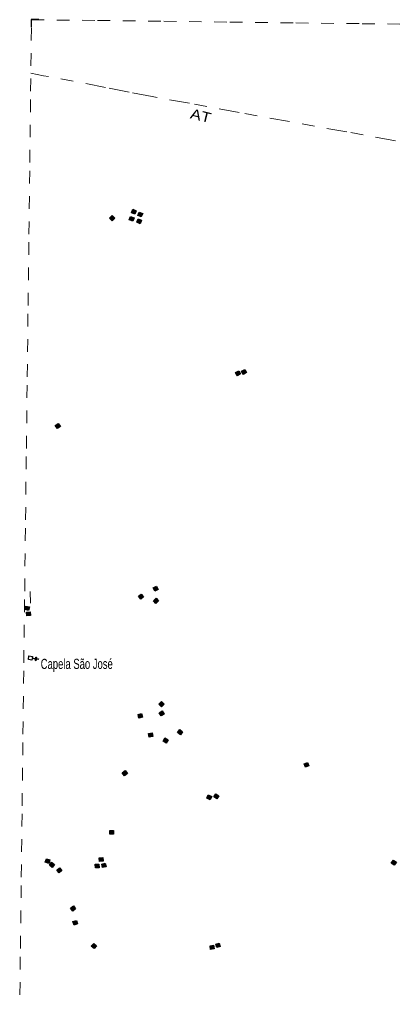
# Model space of a CAD drawing. Extents: x 679 to 705, y 7427.4 to 7455.4.
# Drawn here: x 679.27 to 682.26, y 7447.65 to 7455.38 of the extents above; entities that cross this region are included whole.
import ezdxf
from ezdxf.enums import TextEntityAlignment as Align

# ---------------------------------------------------------------- set-up
doc = ezdxf.new("R2010")
doc.units = 0
doc.header["$LTSCALE"] = 0.032
doc.linetypes.add('DOT_DASHED', pattern=[7.7, 5, -1.2, 0.3, -1.2])
doc.linetypes.add('SHORT_DASHED', pattern=[2.7, 1.5, -1.2])
for name, color, linetype, lineweight in [('2', 7, 'Continuous', 25), ('51', 7, 'Continuous', 13), ('56', 7, 'DOT_DASHED', 13), ('58', 7, 'SHORT_DASHED', 13), ('6', 7, 'Continuous', 25), ('63', 7, 'Continuous', 25)]:
    doc.layers.add(name, color=color, linetype=linetype, lineweight=lineweight)
doc.layers.add('61', color=7, linetype='Continuous')

msp = doc.modelspace()

# ---------------------------------------------------------------- hatches: boundary and pattern name
at = {"layer": '2'}
for points in [[(680.1975, 7453.8664), (680.1867, 7453.8395), (680.1598, 7453.8504), (680.1706, 7453.8772)], [(680.0076, 7453.8279), (680.0285, 7453.8078), (680.0085, 7453.7869), (679.9875, 7453.8069)], [(680.181, 7453.811), (680.1704, 7453.784), (680.1434, 7453.7945), (680.154, 7453.8215)], [(680.2408, 7453.7901), (680.2298, 7453.7633), (680.2029, 7453.7743), (680.214, 7453.8011)], [(680.2492, 7453.8432), (680.2376, 7453.8167), (680.211, 7453.8283), (680.2226, 7453.8549)], [(681.0091, 7452.6009), (681.024, 7452.5761), (680.9991, 7452.5611), (680.9842, 7452.586)], [(681.0563, 7452.6112), (681.0714, 7452.5865), (681.0466, 7452.5714), (681.0315, 7452.5962)], [(679.5811, 7452.1834), (679.5977, 7452.1597), (679.574, 7452.1431), (679.5573, 7452.1668)], [(680.3591, 7450.896), (680.3721, 7450.8701), (680.3461, 7450.8571), (680.3332, 7450.883)], [(680.2378, 7450.8351), (680.256, 7450.8125), (680.2334, 7450.7943), (680.2152, 7450.8168)], [(680.3747, 7450.78), (680.3531, 7450.7606), (680.3337, 7450.7823), (680.3554, 7450.8016)], [(679.3532, 7450.7337), (679.3467, 7450.7054), (679.3185, 7450.7118), (679.3249, 7450.7401)], [(679.3599, 7450.6945), (679.3615, 7450.6656), (679.3326, 7450.6639), (679.3309, 7450.6929)], [(680.3981, 7449.9846), (680.4186, 7449.9641), (680.3981, 7449.9436), (680.3776, 7449.9641)], [(680.2411, 7449.8892), (680.2475, 7449.8609), (680.2192, 7449.8546), (680.2128, 7449.8828)], [(680.4042, 7449.9108), (680.4194, 7449.8861), (680.3948, 7449.8709), (680.3795, 7449.8955)], [(680.3246, 7449.7373), (680.33, 7449.7088), (680.3015, 7449.7034), (680.2961, 7449.7319)], [(680.4256, 7449.6968), (680.4503, 7449.6816), (680.435, 7449.6569), (680.4103, 7449.6722)], [(680.5425, 7449.7627), (680.5653, 7449.7447), (680.5474, 7449.7219), (680.5246, 7449.7399)], [(681.5534, 7449.5029), (681.564, 7449.4758), (681.537, 7449.4653), (681.5264, 7449.4923)], [(680.111, 7449.4388), (680.128, 7449.4153), (680.1045, 7449.3983), (680.0875, 7449.4217)], [(680.7686, 7449.2459), (680.795, 7449.2338), (680.7829, 7449.2074), (680.7565, 7449.2195)], [(680.8279, 7449.2548), (680.8516, 7449.2381), (680.8348, 7449.2144), (680.8112, 7449.2311)], [(679.9896, 7448.9647), (680.0186, 7448.9647), (680.0186, 7448.9357), (679.9896, 7448.9357)], [(679.5147, 7448.7328), (679.506, 7448.7052), (679.4783, 7448.7139), (679.4871, 7448.7416)], [(679.528, 7448.714), (679.5513, 7448.6968), (679.5341, 7448.6735), (679.5107, 7448.6907)], [(679.9032, 7448.7001), (679.9052, 7448.6712), (679.8762, 7448.6693), (679.8743, 7448.6982)], [(679.935, 7448.7513), (679.9372, 7448.7223), (679.9082, 7448.7202), (679.9061, 7448.7491)], [(679.9531, 7448.7068), (679.96, 7448.6787), (679.9318, 7448.6718), (679.9249, 7448.7)], [(682.2329, 7448.7315), (682.2567, 7448.7149), (682.2401, 7448.6911), (682.2163, 7448.7077)], [(679.5912, 7448.6712), (679.6102, 7448.6493), (679.5884, 7448.6303), (679.5693, 7448.6521)], [(679.7009, 7448.3692), (679.7188, 7448.3464), (679.696, 7448.3285), (679.6781, 7448.3514)], [(679.7249, 7448.2541), (679.7339, 7448.2265), (679.7064, 7448.2175), (679.6974, 7448.2451)], [(679.8616, 7448.0725), (679.8834, 7448.0534), (679.8642, 7448.0316), (679.8424, 7448.0508)], [(680.8551, 7448.075), (680.8627, 7448.047), (680.8348, 7448.0394), (680.8271, 7448.0673)], [(680.8105, 7448.058), (680.8154, 7448.0295), (680.7868, 7448.0246), (680.7819, 7448.0531)]]:
    msp.add_hatch(color=256, dxfattribs=at).paths.add_polyline_path(points)

# ---------------------------------------------------------------- linework, layer by layer
for points in [[(680.1975, 7453.8664), (680.1867, 7453.8395), (680.1598, 7453.8504), (680.1706, 7453.8772)], [(680.0076, 7453.8279), (680.0285, 7453.8078), (680.0085, 7453.7869), (679.9875, 7453.8069)], [(680.181, 7453.811), (680.1704, 7453.784), (680.1434, 7453.7945), (680.154, 7453.8215)], [(680.2408, 7453.7901), (680.2298, 7453.7633), (680.2029, 7453.7743), (680.214, 7453.8011)], [(680.2492, 7453.8432), (680.2376, 7453.8167), (680.211, 7453.8283), (680.2226, 7453.8549)], [(681.0091, 7452.6009), (681.024, 7452.5761), (680.9991, 7452.5611), (680.9842, 7452.586)], [(681.0563, 7452.6112), (681.0714, 7452.5865), (681.0466, 7452.5714), (681.0315, 7452.5962)], [(679.5811, 7452.1834), (679.5977, 7452.1597), (679.574, 7452.1431), (679.5573, 7452.1668)], [(680.3591, 7450.896), (680.3721, 7450.8701), (680.3461, 7450.8571), (680.3332, 7450.883)], [(680.2378, 7450.8351), (680.256, 7450.8125), (680.2334, 7450.7943), (680.2152, 7450.8168)], [(680.3747, 7450.78), (680.3531, 7450.7606), (680.3337, 7450.7823), (680.3554, 7450.8016)], [(679.3532, 7450.7337), (679.3467, 7450.7054), (679.3185, 7450.7118), (679.3249, 7450.7401)], [(679.3599, 7450.6945), (679.3615, 7450.6656), (679.3326, 7450.6639), (679.3309, 7450.6929)], [(680.3981, 7449.9846), (680.4186, 7449.9641), (680.3981, 7449.9436), (680.3776, 7449.9641)], [(680.2411, 7449.8892), (680.2475, 7449.8609), (680.2192, 7449.8546), (680.2128, 7449.8828)], [(680.4042, 7449.9108), (680.4194, 7449.8861), (680.3948, 7449.8709), (680.3795, 7449.8955)], [(680.3246, 7449.7373), (680.33, 7449.7088), (680.3015, 7449.7034), (680.2961, 7449.7319)], [(680.4256, 7449.6968), (680.4503, 7449.6816), (680.435, 7449.6569), (680.4103, 7449.6722)], [(680.5425, 7449.7627), (680.5653, 7449.7447), (680.5474, 7449.7219), (680.5246, 7449.7399)], [(681.5534, 7449.5029), (681.564, 7449.4758), (681.537, 7449.4653), (681.5264, 7449.4923)], [(680.111, 7449.4388), (680.128, 7449.4153), (680.1045, 7449.3983), (680.0875, 7449.4217)], [(680.7686, 7449.2459), (680.795, 7449.2338), (680.7829, 7449.2074), (680.7565, 7449.2195)], [(680.8279, 7449.2548), (680.8516, 7449.2381), (680.8348, 7449.2144), (680.8112, 7449.2311)], [(679.9896, 7448.9647), (680.0186, 7448.9647), (680.0186, 7448.9357), (679.9896, 7448.9357)], [(679.5147, 7448.7328), (679.506, 7448.7052), (679.4783, 7448.7139), (679.4871, 7448.7416)], [(679.528, 7448.714), (679.5513, 7448.6968), (679.5341, 7448.6735), (679.5107, 7448.6907)], [(679.9032, 7448.7001), (679.9052, 7448.6712), (679.8762, 7448.6693), (679.8743, 7448.6982)], [(679.935, 7448.7513), (679.9372, 7448.7223), (679.9082, 7448.7202), (679.9061, 7448.7491)], [(679.9531, 7448.7068), (679.96, 7448.6787), (679.9318, 7448.6718), (679.9249, 7448.7)], [(682.2329, 7448.7315), (682.2567, 7448.7149), (682.2401, 7448.6911), (682.2163, 7448.7077)], [(679.5912, 7448.6712), (679.6102, 7448.6493), (679.5884, 7448.6303), (679.5693, 7448.6521)], [(679.7009, 7448.3692), (679.7188, 7448.3464), (679.696, 7448.3285), (679.6781, 7448.3514)], [(679.7249, 7448.2541), (679.7339, 7448.2265), (679.7064, 7448.2175), (679.6974, 7448.2451)], [(679.8616, 7448.0725), (679.8834, 7448.0534), (679.8642, 7448.0316), (679.8424, 7448.0508)], [(680.8551, 7448.075), (680.8627, 7448.047), (680.8348, 7448.0394), (680.8271, 7448.0673)], [(680.8105, 7448.058), (680.8154, 7448.0295), (680.7868, 7448.0246), (680.7819, 7448.0531)]]:
    msp.add_lwpolyline(points, close=True, dxfattribs=at)
at = {"layer": '51'}
msp.add_line((679.3594, 7450.8551), (679.3614, 7450.7625), dxfattribs=at)
at = {"layer": '56'}
msp.add_lwpolyline([(685.0003, 7453.9163), (684.9504, 7453.9212), (684.3878, 7454.0322), (683.544, 7454.178), (682.7017, 7454.3372), (681.8642, 7454.489), (681.0122, 7454.6425), (680.6188, 7454.7152), (680.325, 7454.7692), (680.1415, 7454.8044), (679.9557, 7454.8414), (679.4646, 7454.9339), (679.3645, 7454.9524)], dxfattribs=at)
at = {"layer": '58'}
for points in [[(679.275, 7447.4665), (679.2818, 7448.0315), (679.2885, 7448.5965), (679.2953, 7449.1615), (679.3021, 7449.7265), (679.3088, 7450.2915), (679.3156, 7450.8565), (679.3223, 7451.4214), (679.3291, 7451.9864), (679.3358, 7452.5514), (679.3426, 7453.1164), (679.3493, 7453.6814), (679.3561, 7454.2464), (679.3628, 7454.8114), (679.3696, 7455.3764)], [(679.3696, 7455.3764), (679.8926, 7455.3701), (680.4157, 7455.3638), (680.9388, 7455.3576), (681.4618, 7455.3512), (681.9849, 7455.3449), (682.5079, 7455.3386), (683.031, 7455.3322), (683.5541, 7455.3258), (684.0771, 7455.3194), (684.6002, 7455.313), (685.1233, 7455.3066), (685.6463, 7455.3001), (686.1694, 7455.2937), (686.6925, 7455.2872), (687.2155, 7455.2807), (687.7386, 7455.2741), (688.2617, 7455.2676)]]:
    msp.add_lwpolyline(points, dxfattribs=at)
at = {"layer": '6'}
for points in [[(679.3752, 7450.3247), (679.3732, 7450.3128), (679.3446, 7450.3176), (679.3495, 7450.3462), (679.3781, 7450.3414), (679.376, 7450.3295)], [(679.376, 7450.3295), (679.4028, 7450.3249), (679.4048, 7450.3369), (679.4096, 7450.336), (679.4076, 7450.3241), (679.4238, 7450.3214), (679.423, 7450.3166), (679.4068, 7450.3194), (679.4048, 7450.3075), (679.3999, 7450.3083), (679.402, 7450.3202), (679.3752, 7450.3247)]]:
    msp.add_lwpolyline(points, dxfattribs=at)
at = {"layer": '63'}
msp.add_lwpolyline([(679.4277, 7455.3776), (679.3661, 7455.3776), (679.3661, 7455.3169)], dxfattribs=at)

# ---------------------------------------------------------------- texts
at = {"layer": '61', "width": 1.2}
msp.add_text('AT', height=0.08, rotation=346.231, dxfattribs=at).set_placement((680.6994, 7454.578), align=Align.CENTER)
at = {"layer": '61', "width": 0.7}
msp.add_text('Capela São José', height=0.08, dxfattribs=at).set_placement((679.4424, 7450.2427))

doc.saveas('drawing.dxf')
